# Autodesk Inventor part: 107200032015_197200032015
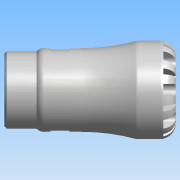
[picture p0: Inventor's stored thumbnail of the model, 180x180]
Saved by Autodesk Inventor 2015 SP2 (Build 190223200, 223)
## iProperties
Created: 2016-12
Part Number: 107200032015_197200032015
Material: PVC-Piping
Description: PLASSON MALE INTEGRAL BRASS THREAD 32X1.1/2" SERIES 1
Document SubType Name: Modeling
Designer: KIM
Mass: 61.7504 g
Surface Area: 140.097 cm^2
Volume: 44.1074 cm^3
Density: 1.4 g/cm^3
Appearance: Smooth - White
Author: KIM
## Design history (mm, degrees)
derived "1072.ipt"
feature "Solid1::1072.ipt"
tag "TaggingFeature1"
body "Solid1"
other parameters: "d0" = 101, "d1" = 23.1, "d2" = 32, "d4" = 58, "d6" = 55, "d8" = 49.3, "d13" = 7.2, "d14" = 7.2, "d15" = 0, "d17" = 360 deg, "d19" = 8 deg, "d20" = 0.64, "d21" = 0.64, "d22" = 8 deg, "d24" = 0, "d26" = 360 deg, "d32" = 5.8, "d33" = 5.8, "d34" = 45.485, "d38" = 19, "d39" = 1.36455, "d42" = 11.2, "d43" = 7.36, "d45" = 14.112, "d46" = 0, "d59" = 360 deg, "d61" = 9.52, "d62" = 0.64, "d64" = 0, "d65" = 0.58, "d68" = 8, "d_" = 32, "E_" = 58, "H_" = 101, "l_" = 55, "R_" = 45.485, "l_2" = 19, "d9" = 9, "d11" = 58
